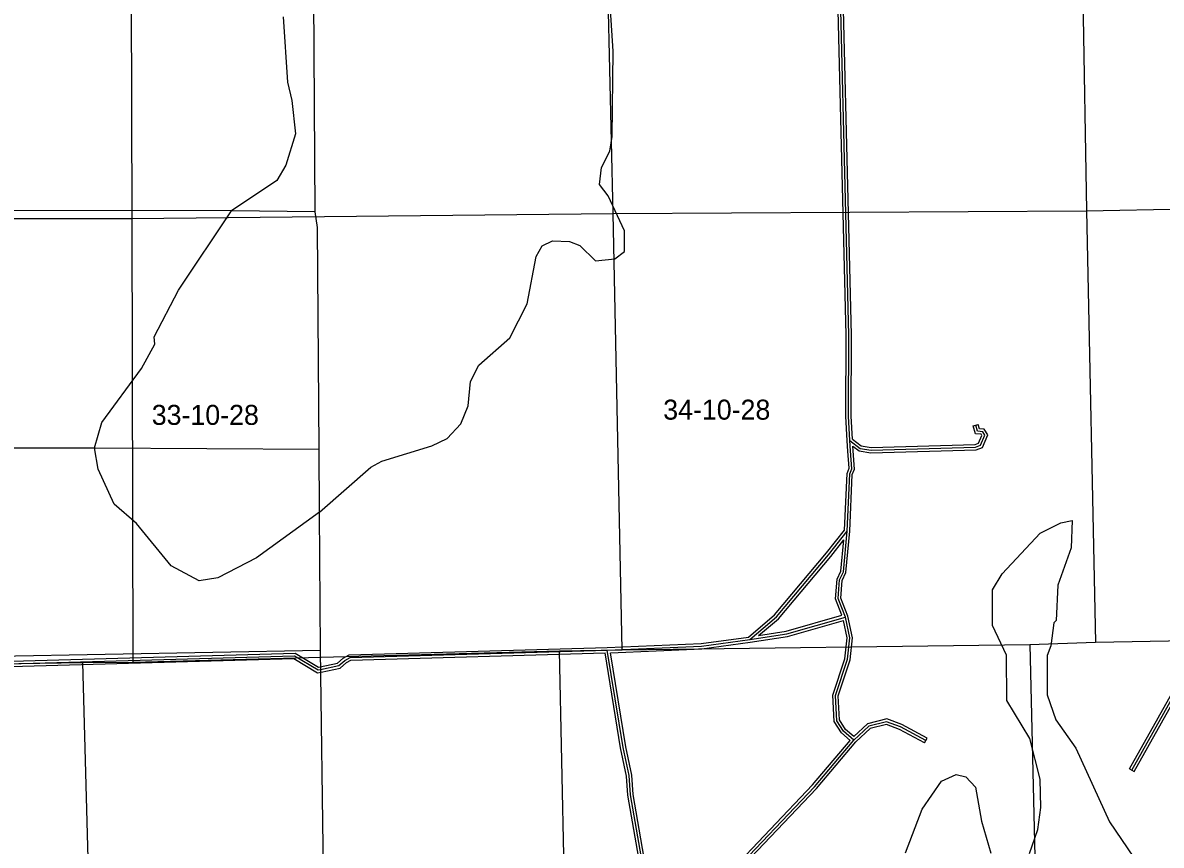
# Model space of a CAD drawing. Extents: x 457167 to 656239, y 1787309 to 1969297.
# Drawn here: x 499317 to 512118, y 1905490 to 1914737 of the extents above; entities that cross this region are included whole.
import ezdxf

# ---------------------------------------------------------------- set-up
doc = ezdxf.new("R2010")
doc.units = 0
for name, color, linetype in [('Level 1', 7, 'Continuous'), ('Level 2', 7, 'Continuous'), ('Level 31', 7, 'Continuous'), ('Level 32', 7, 'Continuous'), ('Level 5', 7, 'Continuous'), ('Level 7', 7, 'Continuous')]:
    doc.layers.add(name, color=color, linetype=linetype)

msp = doc.modelspace()

# ---------------------------------------------------------------- linework, layer by layer
at = {"layer": 'Level 1'}
for p, q in [((511184.61, 1917921.49), (511277.755, 1912623.156)), ((500526.47, 1917769.934), (500544.377, 1912536.369)), ((505954.193, 1912593.258), (505834.664, 1917855.934)), ((511277.755, 1912623.156), (516564.072, 1912719.391)), ((497322.295, 1912537.815), (500544.377, 1912536.369)), ((500544.377, 1912536.369), (505954.193, 1912593.258)), ((500544.377, 1912536.369), (500553.017, 1907548.596)), ((505954.193, 1912593.258), (511277.755, 1912623.156)), ((506055.702, 1907688.333), (505954.193, 1912593.258)), ((511277.755, 1912623.156), (511379.86, 1907772.155)), ((510641.96, 1907746.512), (511379.86, 1907772.155)), ((511379.86, 1907772.155), (516062.388, 1907859.213)), ((500553.017, 1907548.596), (505351.913, 1907674.291)), ((505351.913, 1907674.291), (506055.702, 1907688.333)), ((505466.914, 1902363.727), (505351.913, 1907674.291)), ((506055.702, 1907688.333), (510641.96, 1907746.512)), ((510641.96, 1907746.512), (510762.821, 1902423.898)), ((497300.734, 1907507.73), (499989.248, 1907542.964)), ((499989.248, 1907542.964), (500553.017, 1907548.596)), ((499989.248, 1907542.964), (500127.012, 1902302.055))]:
    msp.add_line(p, q, dxfattribs=at)
at = {"layer": 'Level 31'}
for p, q in [((508624.458, 1909923.091), (508617.613, 1910039.851)), ((502996.92, 1907601.506), (505890, 1907682.37)), ((499020.167, 1907524.728), (502371.721, 1907620.828))]:
    msp.add_line(p, q, dxfattribs=at)
for points in [[(508617.613, 1910039.851), (508600.909, 1910315.201), (508604.21, 1911223.589), (508474.203, 1916559.61), (508375.16, 1916826.563), (508384.921, 1917201.812), (508402.011, 1917263.566)], [(508617.613, 1910039.851), (508732.962, 1909951.386), (508855.893, 1909930.532), (510031.494, 1909966.233), (510087.2, 1909986.742), (510134.376, 1910100.742), (510111.005, 1910139.017), (510052.543, 1910145.067), (510032.467, 1910212.785)], [(508587.495, 1909022.838), (508615.164, 1909664.571), (508640.19, 1909723.02), (508624.458, 1909923.091)], [(511787.204, 1906334.833), (513398.545, 1909205.054), (513428.112, 1909206.395)], [(507491.022, 1907801.724), (507792.133, 1908058.707), (508378.229, 1908757.116), (508587.495, 1909022.838)], [(508567.431, 1908055.969), (508484.66, 1908264.671), (508502.339, 1908472.973), (508544.345, 1908564.446), (508587.495, 1909022.838)], [(507491.022, 1907801.724), (507908.026, 1907866.598), (508567.431, 1908055.969)], [(508662.052, 1906671.9), (508545.786, 1906772.368), (508471.23, 1906889.397), (508455.513, 1907172.744), (508590.65, 1907580.585), (508616.408, 1907822.311), (508567.431, 1908055.969)], [(505890, 1907682.37), (506948.738, 1907728.631), (507491.022, 1907801.724)], [(506419.817, 1904512.82), (506150.754, 1906055.79), (506134.782, 1906272.591), (506069.31, 1906589.961), (505890, 1907682.37)], [(502371.721, 1907620.828), (502637.765, 1907461.17), (502666.717, 1907467.232)], [(502666.717, 1907467.232), (502871.615, 1907510.384), (502938.294, 1907568.656), (502996.92, 1907601.506)], [(509470.757, 1906668.685), (509187.797, 1906819.996), (509029.721, 1906878.807), (508829.573, 1906829.421), (508662.052, 1906671.9)], [(506419.817, 1904512.82), (507264.179, 1905143.256), (508218.409, 1906148.196), (508662.052, 1906671.9)]]:
    msp.add_lwpolyline(points, dxfattribs=at)
at = {"layer": 'Level 32'}
for p, q in [((510003.705, 1910204.258), (510061.23, 1910221.312)), ((508594.527, 1909921.036), (508587.664, 1910038.094)), ((508654.391, 1909925.144), (508651.402, 1909976.129)), ((511761.044, 1906349.52), (513378.592, 1909230.797)), ((499056.883, 1907555.793), (502379.635, 1907651.066)), ((502988.7, 1907631.286), (505889.161, 1907712.358)), ((503005.143, 1907571.722), (505864.641, 1907651.648)), ((499044.095, 1907495.4), (502363.81, 1907590.587)), ((509456.61, 1906642.229), (509484.904, 1906695.141)), ((511761.044, 1906349.52), (511813.364, 1906320.146))]:
    msp.add_line(p, q, dxfattribs=at)
for points in [[(508587.667, 1910038.034), (508570.905, 1910314.346), (508574.209, 1911223.278), (508444.334, 1916553.871), (508345.02, 1916821.556), (508355.026, 1917206.27), (508373.053, 1917271.406)], [(508646.73, 1910055.327), (508630.913, 1910316.056), (508634.213, 1911223.899), (508504.073, 1916565.348), (508405.302, 1916831.57), (508414.816, 1917197.356), (508430.925, 1917255.564)], [(508646.73, 1910055.327), (508745.315, 1909979.72), (508857.966, 1909960.61), (510025.707, 1909996.072), (510064.505, 1910010.356), (510100.825, 1910098.123), (510093.142, 1910110.705), (510029.486, 1910117.291), (510003.705, 1910204.258)], [(508651.402, 1909976.129), (508720.61, 1909923.053), (508853.819, 1909900.455), (510037.281, 1909936.394), (510109.896, 1909963.128), (510167.928, 1910103.361), (510128.868, 1910167.33), (510075.6, 1910172.842), (510061.23, 1910221.312)], [(508557.94, 1909033.797), (508585.427, 1909671.341), (508609.703, 1909728.036), (508594.527, 1909921.036)], [(508617.436, 1909020.783), (508644.9, 1909657.801), (508670.678, 1909718.004), (508654.391, 1909925.144)], [(511813.364, 1906320.146), (513416.548, 1909175.839), (513429.47, 1909176.425)], [(507478.265, 1907830.275), (507770.758, 1908079.906), (508354.948, 1908776.045), (508557.94, 1909033.797)], [(507591.045, 1907847.646), (507813.508, 1908037.508), (508401.51, 1908738.188), (508548.088, 1908924.308)], [(508527.345, 1908075.669), (508454.17, 1908260.174), (508472.889, 1908480.731), (508514.955, 1908572.333), (508548.088, 1908924.308)], [(508596.267, 1908064.639), (508515.151, 1908269.168), (508531.789, 1908465.215), (508573.736, 1908556.558), (508617.436, 1909020.784)], [(507591.045, 1907847.646), (507901.555, 1907895.953), (508527.345, 1908075.669)], [(508661.205, 1906712.281), (508568.728, 1906792.194), (508500.75, 1906898.896), (508485.782, 1907168.716), (508620.141, 1907574.205), (508646.741, 1907823.835), (508596.267, 1908064.639)], [(507495.333, 1907772.031), (507914.497, 1907837.243), (508544.69, 1908018.224)], [(508619.96, 1906668.623), (508522.845, 1906752.542), (508441.711, 1906879.898), (508425.243, 1907176.772), (508561.16, 1907586.966), (508586.075, 1907820.786), (508544.69, 1908018.225)], [(505889.161, 1907712.358), (506946.075, 1907758.545), (507478.264, 1907830.275)], [(505925.08, 1907653.873), (506951.402, 1907698.719), (507495.334, 1907772.031)], [(502379.635, 1907651.066), (502643.122, 1907492.943), (502660.57, 1907496.596)], [(506390.118, 1904508.499), (506120.943, 1906052.102), (506105.006, 1906268.441), (506039.805, 1906584.498), (505864.641, 1907651.648)], [(506440.985, 1904566.065), (506180.564, 1906059.478), (506164.559, 1906276.742), (506098.816, 1906595.423), (505925.08, 1907653.872)], [(502363.81, 1907590.587), (502632.406, 1907429.396), (502672.865, 1907437.868)], [(502660.535, 1907496.588), (502857.77, 1907538.127), (502920.904, 1907593.301), (502988.7, 1907631.287)], [(502672.9, 1907437.876), (502885.46, 1907482.641), (502955.684, 1907544.011), (503005.143, 1907571.721)], [(509484.904, 1906695.141), (509200.157, 1906847.406), (509031.515, 1906910.15), (508814.75, 1906856.663), (508661.205, 1906712.281)], [(509456.61, 1906642.229), (509175.438, 1906792.585), (509027.929, 1906847.466), (508844.395, 1906802.178), (508683.844, 1906651.209)], [(506440.986, 1904566.065), (507244.183, 1905165.766), (508196.069, 1906168.237), (508619.96, 1906668.622)], [(506451.623, 1904499.126), (507284.174, 1905120.746), (508240.75, 1906128.155), (508683.845, 1906651.209)]]:
    msp.add_lwpolyline(points, dxfattribs=at)
at = {"layer": 'Level 5'}
for p, q in [((502606.723, 1912610.99), (502573.445, 1917829.711)), ((501664.744, 1912622.368), (497322.681, 1912627.951)), ((502606.723, 1912610.99), (501664.744, 1912622.368)), ((497312.969, 1909960.321), (500122.314, 1909959.666)), ((500122.314, 1909959.666), (502648.193, 1909943.188)), ((502654.236, 1909234.602), (502648.193, 1909943.188)), ((502665.955, 1907683.976), (502654.236, 1909234.602)), ((497301.063, 1907584.571), (502665.955, 1907683.976)), ((502719.653, 1903632.302), (502665.955, 1907683.976))]:
    msp.add_line(p, q, dxfattribs=at)
msp.add_lwpolyline([(502648.193, 1909943.188), (502631.176, 1912435.856), (502606.723, 1912610.99)], dxfattribs=at)
at = {"layer": 'Level 7'}
for points in [[(502654.236, 1909234.602), (503231.079, 1909741.251), (503356.35, 1909807.555), (503915.437, 1909980.816), (504090.76, 1910063.63), (504241.369, 1910229.866), (504325.357, 1910429.671), (504351.242, 1910704.678), (504443.531, 1910887.783), (504794.642, 1911195.115), (504987.609, 1911577.966), (505089.381, 1912111.171), (505156.43, 1912227.674), (505273.331, 1912285.636), (505465.035, 1912276.679), (505581.609, 1912234.639), (505756.125, 1912059.027), (505972.929, 1912083.311), (506081.56, 1912166.344), (506082.315, 1912399.77), (505900.185, 1912792.166), (505800.54, 1912917.538), (505826.177, 1913109.173), (505918.455, 1913292.278), (505943.993, 1913458.942), (505955.395, 1914417.595), (505883.924, 1915526.55)], [(502246.935, 1914804.626), (502294.609, 1914070.86), (502343.974, 1913862.286), (502384.442, 1913487.027), (502274.966, 1913137.258), (502174.337, 1912962.523), (501664.744, 1912622.368)], [(500122.314, 1909959.666), (500206.59, 1910242.805), (500650.377, 1910849.954), (500801.305, 1911124.562), (500793.233, 1911207.964), (501069.999, 1911732.27), (501664.744, 1912622.368)], [(502654.236, 1909234.602), (501944.022, 1908720.001), (501509.818, 1908496.321), (501301.275, 1908463.637), (500985.055, 1908631.376), (500594.779, 1909107.823), (500345.37, 1909325.355), (500163.209, 1909717.751), (500122.314, 1909959.666)], [(510636.572, 1905399.225), (510729.119, 1905665.691), (510763.245, 1905915.688), (510755.919, 1906232.466), (510640.679, 1906691.355), (510383.626, 1907117.331), (510376.926, 1907625.883), (510219.607, 1907959.859), (510220.88, 1908359.968), (510329.839, 1908543.044), (510756.459, 1909000.17), (510990.271, 1909116.126), (511115.384, 1909140.748), (511106.069, 1908832.331), (510954.674, 1908415.969), (510936.73, 1908015.889), (510911.62, 1907990.978), (510877.465, 1907732.652), (510835.415, 1907624.409), (510834.014, 1907182.578), (510933.14, 1906898.823), (511157.21, 1906581.319), (511538.033, 1905754.814), (512210.074, 1904760.59)], [(509244.405, 1905403.696), (509429.37, 1905894.961), (509647.128, 1906211.021), (509814.08, 1906285.525), (509922.383, 1906260.156), (510030.397, 1906143.124), (510095.855, 1905759.416), (510203.084, 1905400.629)]]:
    msp.add_lwpolyline(points, dxfattribs=at)

# ---------------------------------------------------------------- texts
at = {"layer": 'Level 2'}
for s, p in [('34-10-28', (506518.578, 1910274.997)), ('33-10-28', (500767.293, 1910216.25))]:
    msp.add_text(s, height=225, dxfattribs=at).set_placement(p)

doc.saveas('drawing.dxf')
